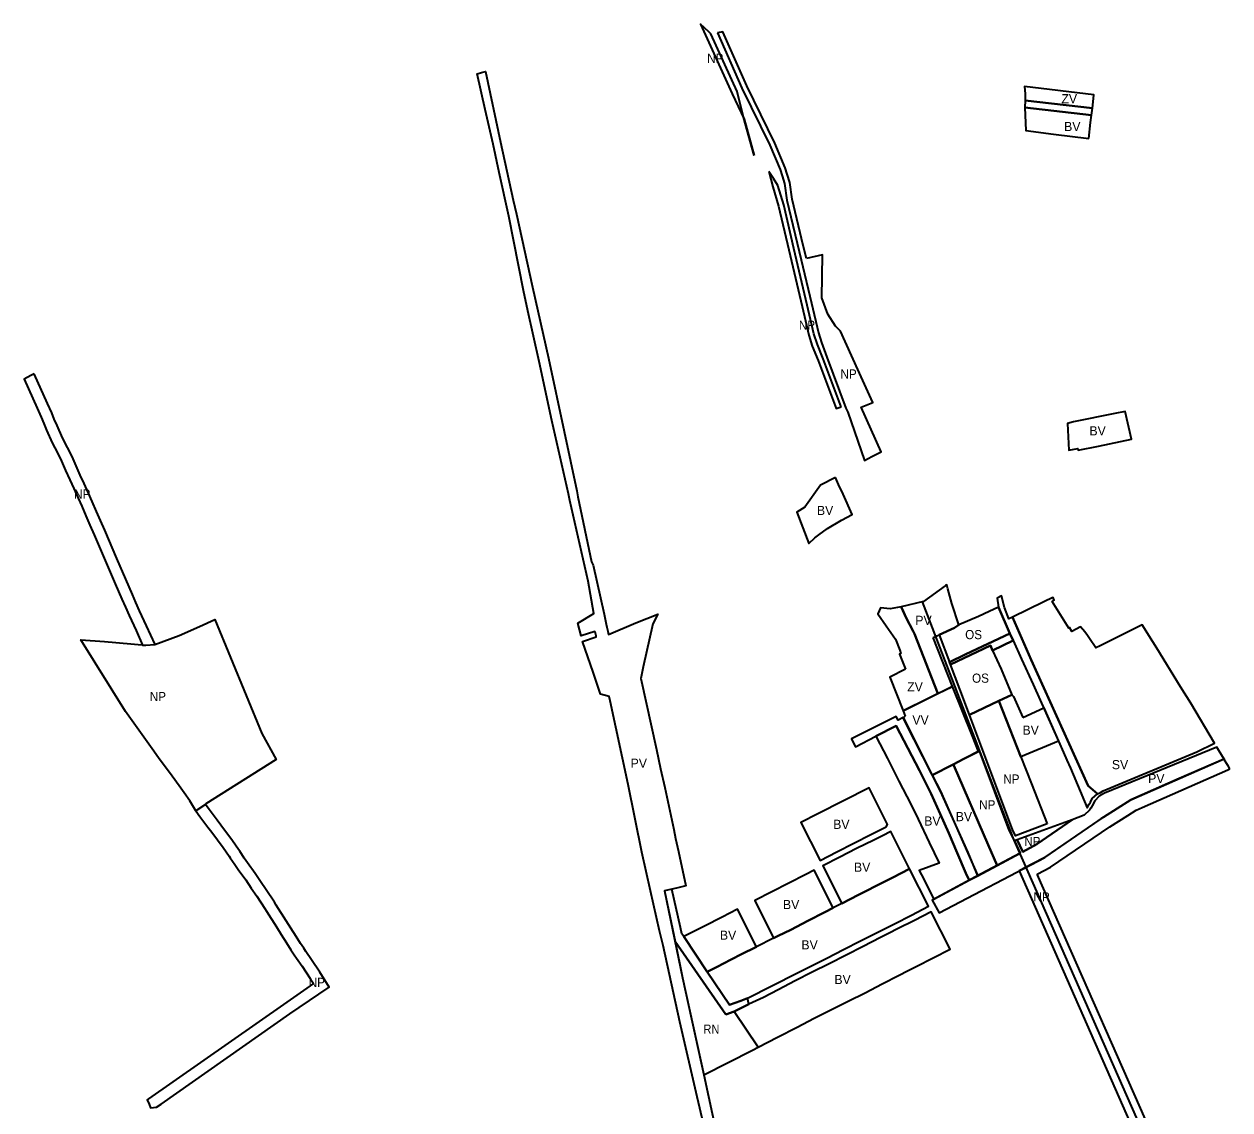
# Model space of a CAD drawing. Extents: x -650276 to -642489, y -1074311 to -1066658.
# Drawn here: x -649558 to -647981, y -1068079 to -1066658 of the extents above; entities that cross this region are included whole.
import ezdxf

# ---------------------------------------------------------------- set-up
doc = ezdxf.new("R2010")
doc.units = 0
doc.header["$LTSCALE"] = 4.8
for name, color, linetype, lineweight in [('15', 7, 'Continuous', 35), ('18', 7, 'Continuous', 35), ('3', 7, 'Continuous', 35), ('40', 7, 'Continuous', 35), ('45', 7, 'Continuous', 35), ('48', 7, 'Continuous', 35), ('54', 7, 'Continuous', 35), ('7', 7, 'Continuous', 35), ('9', 7, 'Continuous', 35)]:
    doc.layers.add(name, color=color, linetype=linetype, lineweight=lineweight)
doc.layers.add('62', color=7, linetype='Continuous')

msp = doc.modelspace()

# ---------------------------------------------------------------- linework, layer by layer
at = {"layer": '15'}
for points in [[(-648662.71, -1068124.76), (-648677.61, -1068061.74), (-648700.16, -1067963.42), (-648722.09, -1067863.84), (-648727.05, -1067844.33), (-648738.7, -1067792.04), (-648749.97, -1067741.49), (-648767.84, -1067652.98), (-648791.68, -1067543.78), (-648792.97, -1067537.86), (-648804.08, -1067534.88), (-648813.94, -1067506.27), (-648827.86, -1067465.86), (-648809.65, -1067459.77), (-648809.97, -1067458.52), (-648811.21, -1067453.52), (-648811.4, -1067452.79), (-648829.54, -1067458.42), (-648834.01, -1067441.81), (-648812.91, -1067429.16), (-648820.39, -1067386.83), (-648844.16, -1067281.37), (-648845.94, -1067272.85), (-648867.82, -1067176.66), (-648884.26, -1067099.63), (-648899.1, -1067033.34), (-648905.06, -1067006.7), (-648917.76, -1066942.65), (-648924.32, -1066909.55), (-648936.7, -1066852.52), (-648944.75, -1066815.41), (-648955.15, -1066770.11), (-648965.39, -1066723.15), (-648959.88, -1066721.59), (-648954.86, -1066720.16), (-648935.19, -1066812.53), (-648918.27, -1066888.41), (-648914.11, -1066907.05), (-648893.02, -1067002.5), (-648872.31, -1067095.5), (-648851.87, -1067191.04), (-648835.29, -1067268.93), (-648833.66, -1067276.77), (-648816.06, -1067361.71), (-648813.81, -1067365.91), (-648799.58, -1067430.4), (-648796.8, -1067443.1), (-648795.88, -1067447.21), (-648794.7, -1067452.46), (-648793.71, -1067456.88), (-648757.97, -1067441.51), (-648728.95, -1067430.33), (-648735.59, -1067442.88), (-648748.53, -1067499.3), (-648751.29, -1067514.57), (-648731.06, -1067607.06), (-648725.8, -1067632.36), (-648720.1, -1067657.12), (-648708.26, -1067712.07), (-648706.08, -1067723.56), (-648702.33, -1067740.84), (-648692.53, -1067785.79), (-648704.614, -1067788.491), (-648710.961, -1067789.906), (-648720.34, -1067792), (-648696.93, -1067905.76), (-648672.31, -1068017.25), (-648668.92, -1068032.96), (-648651.89, -1068111.95)], [(-648268.67, -1067455.43), (-648326.09, -1067482.7), (-648347.51, -1067492.87), (-648346.27, -1067496.14), (-648294.04, -1067471.35)], [(-648294.04, -1067471.35), (-648291.17, -1067477.57), (-648264.34, -1067464.83)], [(-648264.34, -1067464.83), (-648267.21, -1067458.61), (-648268.67, -1067455.43)], [(-648710.961, -1067789.906), (-648720.34, -1067792), (-648706.687, -1067858.345), (-648640, -1067954)], [(-648695.27, -1067852.04), (-648697.7, -1067848.43), (-648699.621, -1067840.06), (-648699.593, -1067840.046), (-648710.96, -1067789.91)], [(-648611.61, -1067932.63), (-648620.658, -1067935.93), (-648635.249, -1067941.252), (-648664.41, -1067897.91), (-648695.27, -1067852.04)], [(-648640, -1067954), (-648629.22, -1067950.214), (-648609.91, -1067940.58), (-648611.61, -1067932.63)]]:
    msp.add_lwpolyline(points, dxfattribs=at)
for points in [[(-648161.58, -1066777.41), (-648160.51, -1066768.4), (-648248.43, -1066758.34), (-648248.77, -1066767.43)], [(-648369.01, -1067460.52), (-648361, -1067457.36), (-648341.15, -1067448.14), (-648335.38, -1067444.07), (-648344.41, -1067416.04), (-648349.67, -1067396.88), (-648351.06, -1067391.62), (-648352.16, -1067392.42), (-648353.35, -1067393.29), (-648381.48, -1067413.68), (-648410.92, -1067420.63), (-648409.61, -1067423.44), (-648404.29, -1067434.9), (-648394.92, -1067452.23), (-648393.17, -1067455.88), (-648362.585, -1067534.205), (-648343.41, -1067524.81), (-648369.01, -1067460.52)], [(-648237.81, -1067522.42), (-648204.88, -1067596.54), (-648198.39, -1067610.97), (-648193.8, -1067621), (-648189.03, -1067631.71), (-648167.48, -1067683.45), (-648164.79, -1067678.96), (-648163.11, -1067676.17), (-648160.68, -1067671.55), (-648153.98, -1067665.43), (-648166.173, -1067654.853), (-648240.51, -1067489.9), (-648265.197, -1067434.03), (-648265.197, -1067434.03), (-648270.02, -1067436.37), (-648275.41, -1067421.3), (-648279.24, -1067406.38), (-648285.08, -1067409.24), (-648283.21, -1067420.88), (-648268.67, -1067455.43), (-648264.34, -1067464.83), (-648253.1, -1067489.23)], [(-648347.51, -1067492.87), (-648326.09, -1067482.7), (-648268.67, -1067455.43), (-648267.21, -1067458.61), (-648264.34, -1067464.83), (-648291.17, -1067477.57), (-648294.04, -1067471.35), (-648319.7, -1067483.53), (-648346.27, -1067496.14)], [(-648359.6, -1067691.58), (-648348.55, -1067716.71), (-648337.32, -1067742.59), (-648326, -1067769), (-648321.623, -1067778.399), (-648310.511, -1067772.476), (-648323.178, -1067741.953), (-648359.213, -1067661.956), (-648405.054, -1067571.837), (-648408.002, -1067565.219), (-648414.73, -1067568.8), (-648417.19, -1067564.02), (-648475.78, -1067593.11), (-648473.34, -1067598.06), (-648470.57, -1067603.69), (-648470.47, -1067603.64), (-648443.83, -1067589.92), (-648417.12, -1067576.17), (-648402.02, -1067605.49), (-648386.91, -1067634.83), (-648371.34, -1067665.08)], [(-647988.235, -1067619.912), (-647995.04, -1067608.56), (-647997.68, -1067604.11), (-648144.83, -1067664.48), (-648151.6, -1067668.12), (-648157.2, -1067674.32), (-648161, -1067680.96), (-648162.69, -1067684), (-648164.09, -1067686.51), (-648171.21, -1067693.37), (-648187.139, -1067699.179), (-648233.264, -1067731.288), (-648251.711, -1067741.124), (-648258.96, -1067725.37), (-648262.632, -1067726.711), (-648255.016, -1067742.886), (-648319.983, -1067777.526), (-648370.113, -1067804.22), (-648360.993, -1067821.027), (-648222.872, -1067748.412), (-648146.127, -1067695.8), (-648110.36, -1067673.133), (-647988.052, -1067619.624)]]:
    msp.add_lwpolyline(points, close=True, dxfattribs=at)
at = {"layer": '18'}
msp.add_lwpolyline([(-648153.98, -1067665.43), (-648149.933, -1067663.646), (-648146.21, -1067661.3), (-648023.96, -1067610.13), (-648000.63, -1067599.14), (-648031.77, -1067546.6), (-648045.04, -1067525.15), (-648076.32, -1067474.6), (-648081.31, -1067466.54), (-648095.28, -1067444.06), (-648133.56, -1067463.2), (-648150.46, -1067471.66), (-648155.85, -1067474.35), (-648164.24, -1067462.15), (-648166.97, -1067458.18), (-648170.38, -1067453.23), (-648175.94, -1067446.89), (-648187.44, -1067452.8), (-648190.23, -1067447.83), (-648191.46, -1067448.59), (-648213.34, -1067413.46), (-648210.48, -1067411.68), (-648211.08, -1067410.6), (-648212.32, -1067408.39), (-648224.19, -1067414.14), (-648265.197, -1067434.03), (-648240.51, -1067489.9), (-648240.51, -1067489.9), (-648166.173, -1067654.853)], close=True, dxfattribs=at)
at = {"layer": '3'}
for points in [[(-648165.33, -1066807.74), (-648162.8, -1066786.8), (-648161.58, -1066777.41), (-648248.77, -1066767.43), (-648247.78, -1066797.53), (-648211.58, -1066802.18)], [(-648185.185, -1067178.687), (-648193.02, -1067180.66), (-648191.44, -1067215.62), (-648179.42, -1067213.37), (-648179, -1067215.71), (-648152.5, -1067210.23), (-648109.1, -1067201.21), (-648117.562, -1067165.197), (-648131.01, -1067167.84)], [(-648496.55, -1067251.53), (-648516.47, -1067261.54), (-648536.84, -1067290.29), (-648547.17, -1067296.68), (-648531.51, -1067337.57), (-648523.55, -1067330.33), (-648518.55, -1067326.3), (-648507.25, -1067318.35), (-648488.66, -1067307.11), (-648474.69, -1067299.66), (-648486.79, -1067273.26), (-648492.62, -1067260.53)], [(-648397.98, -1067678.79), (-648388.526, -1067698.603), (-648373.99, -1067728.95), (-648361.08, -1067755.88), (-648387.04, -1067765.67), (-648384.25, -1067771.07), (-648367.811, -1067802.994), (-648321.623, -1067778.399), (-648326, -1067769), (-648337.32, -1067742.59), (-648348.55, -1067716.71), (-648359.6, -1067691.58), (-648371.34, -1067665.08), (-648386.91, -1067634.83), (-648402.02, -1067605.49), (-648417.12, -1067576.17), (-648443.83, -1067589.92), (-648428.7, -1067619.24), (-648413.57, -1067648.57)], [(-648342.697, -1067626.806), (-648369.949, -1067640.851), (-648359.213, -1067661.956), (-648310.511, -1067772.476), (-648285.254, -1067759.008), (-648296.891, -1067732.172), (-648342.023, -1067628.096)], [(-648519.63, -1067691.58), (-648541.86, -1067702.86), (-648516.73, -1067752.57), (-648494.84, -1067741.06), (-648472.5, -1067729.76), (-648450.23, -1067718.32), (-648430.17, -1067708.33), (-648428.67, -1067705.52), (-648452.72, -1067657.62)], [(-648491.14, -1067748.02), (-648513.23, -1067759.38), (-648488.49, -1067808.76), (-648466.36, -1067797.5), (-648455.32, -1067791.85), (-648444.28, -1067786.19), (-648421.84, -1067774.66), (-648410.78, -1067768.98), (-648399.64, -1067763.26), (-648424.14, -1067714.34), (-648435.34, -1067720.01), (-648446.58, -1067725.71), (-648468.97, -1067736.91), (-648480.06, -1067742.47)], [(-648577.78, -1067854.07), (-648571.69, -1067851.06), (-648555.32, -1067842.99), (-648532.98, -1067831.54), (-648510.82, -1067820.19), (-648499.7, -1067814.37), (-648524.44, -1067765.11), (-648535.61, -1067770.85), (-648557.84, -1067782.26), (-648580.14, -1067793.61), (-648602.3, -1067804.83)], [(-648644.095, -1067887.6), (-648620.51, -1067875.63), (-648600.14, -1067865.29), (-648624.76, -1067816.11), (-648645.11, -1067826.48), (-648668.085, -1067838.186), (-648675.26, -1067841.84), (-648695.27, -1067852.04), (-648664.41, -1067897.91), (-648650.68, -1067890.94)]]:
    msp.add_lwpolyline(points, close=True, dxfattribs=at)
for points in [[(-648282.863, -1067543.596), (-648265.757, -1067535.555), (-648263.7, -1067537.93), (-648251.33, -1067565.28)], [(-648251.33, -1067565.28), (-648224.16, -1067552.55), (-648204.88, -1067596.54), (-648254.04, -1067616.96), (-648282.863, -1067543.596)], [(-648611.61, -1067932.63), (-648611.61, -1067932.63), (-648547.09, -1067899.87), (-648530.81, -1067891.61), (-648508.22, -1067880.38), (-648486.09, -1067868.98), (-648463.91, -1067857.74), (-648441.47, -1067846.37), (-648419.44, -1067835.3), (-648397.04, -1067823.85), (-648374.84, -1067812.43), (-648399.64, -1067763.26), (-648421.84, -1067774.66)], [(-648421.84, -1067774.66), (-648444.28, -1067786.19), (-648455.32, -1067791.85), (-648466.36, -1067797.5), (-648488.49, -1067808.76)], [(-648488.49, -1067808.76), (-648499.7, -1067814.37), (-648510.82, -1067820.19), (-648532.98, -1067831.54), (-648555.32, -1067842.99), (-648571.69, -1067851.06)], [(-648572.5, -1067983.59), (-648546.76, -1067970.44), (-648524.72, -1067958.93), (-648502.59, -1067948), (-648480.12, -1067936.55), (-648457.87, -1067925.4), (-648435.55, -1067913.84), (-648413.41, -1067902.53), (-648402.29, -1067897.02), (-648391.08, -1067891.24), (-648368.78, -1067879.75), (-648346.57, -1067868.56), (-648371.27, -1067819.47), (-648393.35, -1067830.81), (-648415.69, -1067841.98), (-648426.65, -1067847.64), (-648437.89, -1067853.4), (-648460.33, -1067864.88), (-648482.5, -1067876.22), (-648504.92, -1067887.52), (-648527.33, -1067898.74), (-648549.44, -1067910.07), (-648571.88, -1067921.71), (-648591.04, -1067931.62), (-648609.91, -1067940.58)], [(-648571.69, -1067851.06), (-648577.78, -1067854.07), (-648600.14, -1067865.29)], [(-648600.14, -1067865.29), (-648620.51, -1067875.63), (-648644.095, -1067887.6)], [(-648644.095, -1067887.6), (-648650.68, -1067890.94), (-648664.41, -1067897.91), (-648635.249, -1067941.252), (-648620.658, -1067935.93), (-648611.61, -1067932.63)], [(-648609.91, -1067940.58), (-648629.22, -1067950.214), (-648597.93, -1067996.72), (-648572.5, -1067983.59)]]:
    msp.add_lwpolyline(points, dxfattribs=at)
at = {"layer": '40'}
for points in [[(-648160.51, -1066768.4), (-648159.66, -1066759.8), (-648158.49, -1066750.93), (-648249.44, -1066739.8), (-648248.34, -1066749.33), (-648248.43, -1066758.34)], [(-648405.27, -1067502.27), (-648425.5, -1067512.73), (-648408.26, -1067556.58), (-648362.585, -1067534.205), (-648393.17, -1067455.88), (-648394.92, -1067452.23), (-648404.29, -1067434.9), (-648410.92, -1067420.63), (-648425, -1067423.05), (-648437.75, -1067421.99), (-648441.48, -1067429.63), (-648430.4, -1067445.51), (-648418.3, -1067462.86), (-648412.46, -1067477.42), (-648411.25, -1067481.73), (-648412.89, -1067482.55)]]:
    msp.add_lwpolyline(points, close=True, dxfattribs=at)
at = {"layer": '45'}
msp.add_lwpolyline([(-648405.41, -1067563.84), (-648408.002, -1067565.219), (-648369.949, -1067640.851), (-648342.697, -1067626.806), (-648328.54, -1067619.51), (-648309.522, -1067609.713), (-648317.43, -1067590), (-648343.41, -1067524.81), (-648408.26, -1067556.58)], close=True, dxfattribs=at)
at = {"layer": '48'}
for points in [[(-648602.97, -1066830.11), (-648616.86, -1066779.79), (-648625.44, -1066746.45), (-648659.95, -1066670.89), (-648662.46, -1066668.53), (-648673.407, -1066658.275), (-648631.791, -1066749.394)], [(-648534.701, -1066965.077), (-648538.812, -1066947.891), (-648553.323, -1066887.238), (-648556.637, -1066865.397), (-648559.94, -1066854.66), (-648562.542, -1066846.219), (-648576.145, -1066813.802), (-648612.763, -1066739.165), (-648643.925, -1066668.483), (-648651.042, -1066669.551), (-648651.1, -1066669.56)], [(-648651.1, -1066669.56), (-648619.11, -1066742.12), (-648582.52, -1066816.7)], [(-648631.791, -1066749.394), (-648616.104, -1066782.727), (-648602.97, -1066830.11)], [(-648582.52, -1066816.7), (-648569.13, -1066848.61), (-648566.63, -1066856.72), (-648563.48, -1066866.96), (-648560.2, -1066888.58), (-648541.521, -1066966.657), (-648541.52, -1066966.657)], [(-648571.96, -1066869.37), (-648577.99, -1066860.17), (-648583.94, -1066851.11)], [(-648583.94, -1066851.11), (-648578.702, -1066871.259), (-648571.167, -1066896.326), (-648557.816, -1066953.444)], [(-648489.1, -1067158.84), (-648512.95, -1067095.97), (-648520.4, -1067077.42), (-648524.93, -1067063.35), (-648533.66, -1067026), (-648551, -1066951.85), (-648564.4, -1066894.52), (-648571.96, -1066869.37)], [(-648557.816, -1066953.444), (-648540.476, -1067027.594), (-648531.681, -1067065.222)], [(-648541.52, -1066966.657), (-648528.01, -1067023.13), (-648518.72, -1067061.99), (-648514.86, -1067074.83), (-648507.88, -1067093.9), (-648483.31, -1067160.63), (-648480.57, -1067166.13), (-648458.73, -1067229.1), (-648449.03, -1067224.14), (-648437.02, -1067217.99), (-648462.97, -1067159.24), (-648447.66, -1067153.25), (-648467.56, -1067110.02), (-648490.23, -1067060.06), (-648496.87, -1067053.5), (-648506.78, -1067037.81), (-648514.38, -1067016.2), (-648513.842, -1066960.243), (-648534.701, -1066965.077)], [(-648531.681, -1067065.222), (-648526.988, -1067079.8), (-648519.471, -1067098.516), (-648495.644, -1067161.326), (-648489.1, -1067158.84)], [(-648321.361, -1067561.69), (-648282.863, -1067543.596), (-648254.04, -1067616.96)], [(-648219.86, -1067704.42), (-648235.78, -1067710.79), (-648261.25, -1067720.39), (-648265.08, -1067712.06), (-648311.95, -1067586.45), (-648321.361, -1067561.69)], [(-648254.04, -1067616.96), (-648247.53, -1067633.53), (-648240.19, -1067652.12), (-648219.86, -1067704.42)], [(-647980.561, -1067632.719), (-647982.95, -1067628.73), (-647988.334, -1067619.747), (-648046.773, -1067645.314)], [(-648095.475, -1067682.994), (-647983.06, -1067633.813), (-647980.561, -1067632.719)], [(-648046.773, -1067645.314), (-648110.36, -1067673.133), (-648146.127, -1067695.8), (-648146.146, -1067695.813), (-648149.529, -1067698.132), (-648222.53, -1067748.178)], [(-648232.676, -1067770.513), (-648215.115, -1067761.28), (-648137.869, -1067708.325), (-648114.323, -1067693.403), (-648103.298, -1067686.416), (-648095.475, -1067682.994)], [(-648222.53, -1067748.178), (-648222.872, -1067748.412), (-648238.748, -1067756.759)], [(-648238.748, -1067756.759), (-648256.499, -1067766.091), (-648079.002, -1068168.139)], [(-648079.002, -1068168.139), (-648061.329, -1068158.649), (-648232.676, -1067770.513)]]:
    msp.add_lwpolyline(points, dxfattribs=at)
for points in [[(-649545.203, -1067115.647), (-649549.7, -1067118.05), (-649558.469, -1067122.73), (-649541.537, -1067160.722), (-649536.075, -1067172.622), (-649532.831, -1067180.855), (-649529.013, -1067189.389), (-649521.663, -1067206.124), (-649514.869, -1067218.957), (-649509.44, -1067230.141), (-649504.224, -1067242.225), (-649498.572, -1067254.427), (-649493.526, -1067265.611), (-649487.812, -1067278.312), (-649482.963, -1067288.934), (-649477.677, -1067301.655), (-649472.327, -1067313.644), (-649466.703, -1067326.24), (-649451.059, -1067363.074), (-649439.265, -1067390.397), (-649430.531, -1067410.689), (-649425.804, -1067421.21), (-649421.071, -1067431.944), (-649411.913, -1067451.746), (-649403.34, -1067470.579), (-649399.39, -1067470.93), (-649387.4, -1067469.98), (-649387.17, -1067469.894), (-649398.28, -1067445.49), (-649407.4, -1067425.77), (-649412.1, -1067415.11), (-649416.8, -1067404.65), (-649425.49, -1067384.46), (-649437.27, -1067357.17), (-649452.95, -1067320.25), (-649458.63, -1067307.53), (-649463.9, -1067295.72), (-649469.21, -1067282.94), (-649474.15, -1067272.12), (-649479.85, -1067259.45), (-649484.93, -1067248.19), (-649490.53, -1067236.1), (-649495.8, -1067223.89), (-649501.49, -1067212.17), (-649508.15, -1067199.59), (-649515.3, -1067183.31), (-649519, -1067175.04), (-649522.27, -1067166.74), (-649527.87, -1067154.54)], [(-649333.74, -1067687.4), (-649335.26, -1067685.21), (-649341.81, -1067674.33), (-649349.12, -1067663.84), (-649355.46, -1067654.85), (-649364.69, -1067641.98), (-649382.53, -1067618.33), (-649391.04, -1067606.27), (-649393.23, -1067603.28), (-649425.69, -1067557.7), (-649484.28, -1067463.88), (-649453.39, -1067466.13), (-649399.39, -1067470.93), (-649387.4, -1067469.98), (-649355.44, -1067457.94), (-649329.068, -1067446.175), (-649308.75, -1067437.11), (-649247.518, -1067586.255), (-649228.52, -1067620.294), (-649320.47, -1067678.44)], [(-648342.023, -1067628.096), (-648296.891, -1067732.172), (-648285.254, -1067759.008), (-648255.016, -1067742.886), (-648265.614, -1067720.378), (-648269.27, -1067712.6), (-648308.43, -1067609.15), (-648328.54, -1067619.51), (-648342.697, -1067626.806)], [(-649321.3, -1067679), (-649333.74, -1067687.4), (-649328.34, -1067694.79), (-649317.99, -1067708.85), (-649312.91, -1067715.45), (-649298.02, -1067735.58), (-649290.15, -1067746.92), (-649288.63, -1067748.97), (-649282.85, -1067757.79), (-649278.14, -1067764.31), (-649268.46, -1067777.97), (-649261.48, -1067788.47), (-649253.98, -1067799.2), (-649243.37, -1067815.17), (-649241.28, -1067818.7), (-649228.27, -1067839.26), (-649222.11, -1067849.12), (-649215.32, -1067859.99), (-649209.39, -1067869.34), (-649204.87, -1067875.85), (-649202.02, -1067880.07), (-649194.77, -1067890.67), (-649184, -1067906.88), (-649179.96, -1067913.35), (-649219.088, -1067940.964), (-649395.729, -1068064.23), (-649397.466, -1068065.442), (-649394.83, -1068071.05), (-649392.88, -1068075.9), (-649385.41, -1068075.32), (-649379.295, -1068071.053), (-649210.54, -1067953.29), (-649172.99, -1067927.41), (-649159.179, -1067918.309), (-649171.389, -1067898.756), (-649182.332, -1067882.285), (-649189.614, -1067871.638), (-649192.493, -1067867.375), (-649196.89, -1067861.042), (-649202.625, -1067852), (-649209.388, -1067841.173), (-649215.571, -1067831.276), (-649228.486, -1067810.867), (-649230.661, -1067807.193), (-649241.584, -1067790.752), (-649249.085, -1067780.02), (-649256.092, -1067769.48), (-649265.941, -1067755.582), (-649270.491, -1067749.283), (-649276.322, -1067740.385), (-649277.961, -1067738.175), (-649285.826, -1067726.842), (-649300.936, -1067706.414), (-649306.005, -1067699.828), (-649316.244, -1067685.919)], [(-648258.96, -1067725.37), (-648251.711, -1067741.124), (-648233.264, -1067731.288), (-648187.139, -1067699.179)]]:
    msp.add_lwpolyline(points, close=True, dxfattribs=at)
at = {"layer": '54'}
msp.add_lwpolyline([(-648383.36, -1067413.938), (-648264.607, -1067722.965), (-648014.937, -1068288.491)], dxfattribs=at)
at = {"layer": '7'}
msp.add_lwpolyline([(-648640, -1067954), (-648706.687, -1067858.345), (-648696.93, -1067905.76), (-648668.92, -1068032.96), (-648605.323, -1068000.463), (-648597.93, -1067996.72), (-648629.22, -1067950.214)], close=True, dxfattribs=at)
at = {"layer": '9'}
msp.add_lwpolyline([(-648268.67, -1067455.43), (-648283.21, -1067420.88), (-648295.66, -1067426.76), (-648309.57, -1067433.34), (-648335.38, -1067444.07), (-648341.15, -1067448.14), (-648361, -1067457.36), (-648347.51, -1067492.87), (-648326.09, -1067482.7)], close=True, dxfattribs=at)
for points in [[(-648346.27, -1067496.14), (-648294.04, -1067471.35), (-648291.172, -1067477.571), (-648291.17, -1067477.57), (-648279.86, -1067502.11)], [(-648321.361, -1067561.69), (-648334.09, -1067528.2), (-648346.27, -1067496.14)], [(-648279.86, -1067502.11), (-648265.757, -1067535.555), (-648282.863, -1067543.596), (-648321.361, -1067561.69)]]:
    msp.add_lwpolyline(points, dxfattribs=at)

# ---------------------------------------------------------------- texts
at = {"layer": '62'}
for s, width, p in [('NP', 0.95, (-648664.583, -1066709.041)), ('NP', 0.95, (-648544.583, -1067058.041)), ('NP', 0.95, (-648490.15, -1067121.972)), ('NP', 0.95, (-649492.985, -1067278.967)), ('OS', 0.95, (-648326.942, -1067462.923)), ('OS', 0.95, (-648317.942, -1067519.923)), ('NP', 0.95, (-649393.985, -1067543.967)), ('NP', 0.95, (-648277.019, -1067651.94)), ('NP', 0.95, (-648308.631, -1067685.579)), ('NP', 0.95, (-648249.631, -1067733.579)), ('NP', 0.95, (-648237.583, -1067806.041)), ('NP', 0.95, (-649185.985, -1067917.967)), ('RN', 0.9, (-648669.473, -1067979.058))]:
    msp.add_text(s, height=12, dxfattribs=dict(at, width=width)).set_placement(p)
for s, p in [('ZV', (-648201.026, -1066761.906)), ('BV', (-648197.475, -1066798.284)), ('BV', (-648164.386, -1067196.331)), ('BV', (-648520.956, -1067300.498)), ('PV', (-648392.213, -1067444.317)), ('ZV', (-648402.918, -1067531.307)), ('VV', (-648396.075, -1067574.614)), ('BV', (-648251.942, -1067587.923)), ('PV', (-648764.767, -1067631.209)), ('SV', (-648135.028, -1067633.035)), ('PV', (-648087.517, -1067651.275)), ('BV', (-648339.301, -1067701.063)), ('BV', (-648499.724, -1067711.153)), ('BV', (-648380.551, -1067706.775)), ('BV', (-648472.48, -1067767.243)), ('BV', (-648565.429, -1067816.121)), ('BV', (-648647.961, -1067856.185)), ('BV', (-648541.281, -1067868.87)), ('BV', (-648498.112, -1067914.191))]:
    msp.add_text(s, height=12, dxfattribs=at).set_placement(p)

doc.saveas('drawing.dxf')
